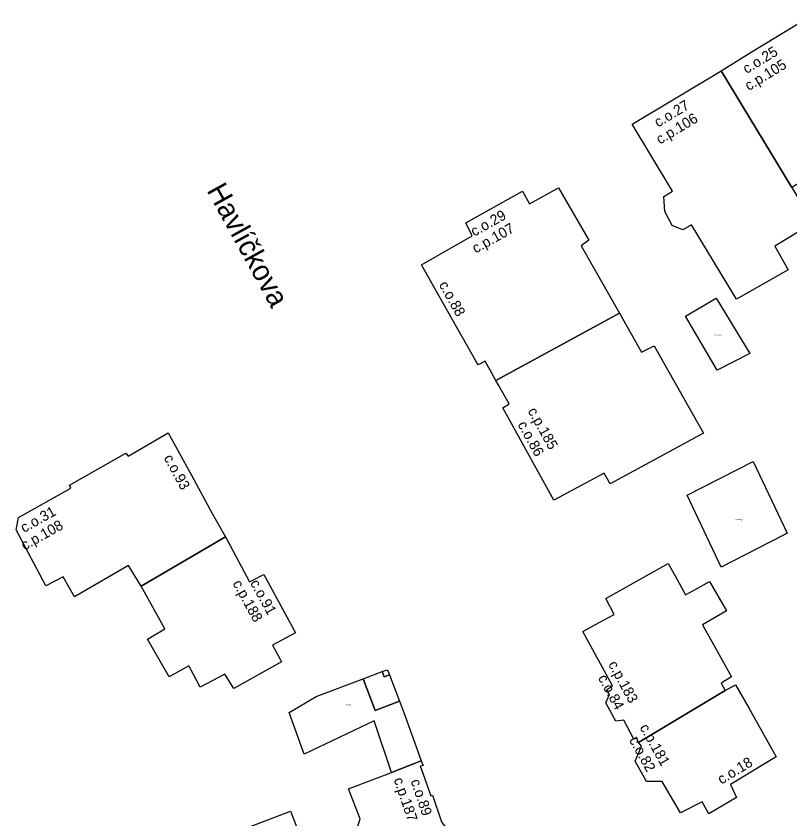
# Model space of a CAD drawing. Extents: x -600391 to -599491, y -1160176 to -1159402.
# Drawn here: x -600294.6 to -600219.9, y -1159654.1 to -1159576.6 of the extents above; entities that cross this region are included whole.
import ezdxf

# ---------------------------------------------------------------- set-up
doc = ezdxf.new("R2010")
doc.units = 0
for name, color, linetype in [('Level 10', 7, 'Continuous'), ('Level 11', 7, 'Continuous'), ('Level 12', 7, 'Continuous'), ('Level 24', 7, 'Continuous'), ('Level 25', 7, 'Continuous'), ('Level 61', 7, 'Continuous'), ('Level 62', 7, 'Continuous')]:
    doc.layers.add(name, color=color, linetype=linetype)

msp = doc.modelspace()

# ---------------------------------------------------------------- linework, layer by layer
at = {"layer": 'Level 61'}
for points in [[(-600223.41, -1159579.93), (-600217.94, -1159576.62)], [(-600226.56, -1159581.89), (-600223.41, -1159579.93)], [(-600235.15, -1159587.05), (-600226.82, -1159582.05)], [(-600226.82, -1159582.05), (-600226.56, -1159581.89)], [(-600219.75, -1159593.15), (-600226.56, -1159581.89)], [(-600226.56, -1159581.89), (-600219.75, -1159593.15)], [(-600231.24, -1159593.51), (-600235.15, -1159587.05)], [(-600251.18, -1159596.55), (-600245.74, -1159593.51)], [(-600245.74, -1159593.51), (-600245.05, -1159594.74)], [(-600245.05, -1159594.74), (-600242.26, -1159593.19)], [(-600242.26, -1159593.19), (-600239.31, -1159598.24)], [(-600232.08, -1159594.02), (-600231.24, -1159593.51)], [(-600232.01, -1159595.46), (-600232.08, -1159594.02)], [(-600231.28, -1159596.82), (-600232.01, -1159595.46)], [(-600250.59, -1159597.82), (-600251.18, -1159596.55)], [(-600229.42, -1159596.75), (-600230.25, -1159597.24)], [(-600225.09, -1159603.94), (-600229.42, -1159596.75)], [(-600217.72, -1159596.61), (-600221.38, -1159598.8)], [(-600230.25, -1159597.24), (-600231.28, -1159596.82)], [(-600255.47, -1159600.61), (-600250.59, -1159597.82)], [(-600239.31, -1159598.24), (-600240.07, -1159598.78)], [(-600240.07, -1159598.78), (-600236.37, -1159605.27)], [(-600221.38, -1159598.8), (-600220.1, -1159601.1)], [(-600255.06, -1159601.34), (-600255.47, -1159600.61)], [(-600254.31, -1159602.67), (-600255.06, -1159601.34)], [(-600220.1, -1159601.1), (-600225.09, -1159603.94)], [(-600250.16, -1159610.01), (-600254.31, -1159602.67)], [(-600229.99, -1159605.58), (-600227.04, -1159603.82)], [(-600227.04, -1159603.82), (-600223.81, -1159609.18)], [(-600248.29, -1159611.76), (-600236.37, -1159605.27)], [(-600236.37, -1159605.27), (-600248.29, -1159611.76)], [(-600236.37, -1159605.27), (-600234.94, -1159607.77)], [(-600226.93, -1159610.77), (-600229.99, -1159605.58)], [(-600234.94, -1159607.77), (-600234.25, -1159609.05)], [(-600234.25, -1159609.05), (-600233.01, -1159608.43)], [(-600233.01, -1159608.43), (-600232.11, -1159610.04)], [(-600223.81, -1159609.18), (-600226.93, -1159610.77)], [(-600249.34, -1159609.89), (-600250.01, -1159610.27)], [(-600248.29, -1159611.76), (-600249.34, -1159609.89)], [(-600250.01, -1159610.27), (-600250.16, -1159610.01)], [(-600232.11, -1159610.04), (-600228.28, -1159616.85)], [(-600248.08, -1159612.14), (-600248.29, -1159611.76)], [(-600247.02, -1159614.02), (-600248.08, -1159612.14)], [(-600247.63, -1159614.4), (-600247.02, -1159614.02)], [(-600242.69, -1159623.31), (-600247.63, -1159614.4)], [(-600283.77, -1159619.07), (-600279.92, -1159616.82)], [(-600279.92, -1159616.82), (-600278.15, -1159620.03)], [(-600228.28, -1159616.85), (-600237.27, -1159621.75)], [(-600289.41, -1159621.85), (-600283.98, -1159618.78)], [(-600283.98, -1159618.78), (-600283.77, -1159619.07)], [(-600278.15, -1159620.03), (-600277.67, -1159620.91)], [(-600229.84, -1159622.84), (-600223.48, -1159619.59)], [(-600223.48, -1159619.59), (-600220.2, -1159626.51)], [(-600237.85, -1159620.71), (-600242.69, -1159623.31)], [(-600237.27, -1159621.75), (-600237.85, -1159620.71)], [(-600277.67, -1159620.91), (-600275.66, -1159624.6)], [(-600294.33, -1159624.97), (-600289.29, -1159622.14)], [(-600289.29, -1159622.14), (-600289.41, -1159621.85)], [(-600226.57, -1159629.76), (-600229.84, -1159622.84)], [(-600275.66, -1159624.6), (-600274.39, -1159626.85)], [(-600294.58, -1159626.18), (-600294.33, -1159624.97)], [(-600291.7, -1159631.56), (-600294.58, -1159626.18)], [(-600282.5, -1159631.62), (-600274.39, -1159626.85)], [(-600274.39, -1159626.85), (-600282.5, -1159631.62)], [(-600274.39, -1159626.85), (-600274.16, -1159627.27)], [(-600220.6, -1159626.71), (-600226.57, -1159629.76)], [(-600220.2, -1159626.51), (-600220.6, -1159626.71)], [(-600274.16, -1159627.27), (-600272.05, -1159631.18)], [(-600283.72, -1159629.61), (-600288.93, -1159632.63)], [(-600282.5, -1159631.62), (-600283.72, -1159629.61)], [(-600237.68, -1159632.8), (-600231.67, -1159629.41)], [(-600231.67, -1159629.41), (-600231, -1159630.62)], [(-600290.03, -1159630.71), (-600291.7, -1159631.56)], [(-600288.93, -1159632.63), (-600290.03, -1159630.71)], [(-600272.05, -1159631.18), (-600270.69, -1159630.49)], [(-600270.69, -1159630.49), (-600267.61, -1159636.1)], [(-600231, -1159630.62), (-600229.99, -1159632.43)], [(-600280.22, -1159635.71), (-600282.5, -1159631.62)], [(-600228.94, -1159631.85), (-600227.68, -1159631.16)], [(-600227.68, -1159631.16), (-600226.04, -1159633.98)], [(-600229.99, -1159632.43), (-600228.94, -1159631.85)], [(-600236.87, -1159634.33), (-600237.68, -1159632.8)], [(-600238.32, -1159635.1), (-600236.87, -1159634.33)], [(-600226.04, -1159633.98), (-600228.37, -1159635.33)], [(-600239.92, -1159635.98), (-600238.32, -1159635.1)], [(-600228.37, -1159635.33), (-600225.56, -1159640.36)], [(-600281.91, -1159636.71), (-600280.22, -1159635.71)], [(-600267.61, -1159636.1), (-600269.84, -1159637.3)], [(-600237.04, -1159641.22), (-600239.92, -1159635.98)], [(-600279.82, -1159640.36), (-600281.91, -1159636.71)], [(-600269.84, -1159637.3), (-600269.1, -1159638.65)], [(-600277.91, -1159639.28), (-600278.65, -1159639.72)], [(-600277.46, -1159640.14), (-600277.91, -1159639.28)], [(-600268.97, -1159638.89), (-600273.58, -1159641.47)], [(-600269.1, -1159638.65), (-600268.97, -1159638.89)], [(-600278.65, -1159639.72), (-600279.82, -1159640.36)], [(-600276.81, -1159641.34), (-600277.46, -1159640.14)], [(-600274.43, -1159640.09), (-600276.81, -1159641.34)], [(-600273.58, -1159641.47), (-600274.43, -1159640.09)], [(-600261.1, -1159640.54), (-600259.26, -1159639.85)], [(-600259.26, -1159639.85), (-600258.75, -1159639.66)], [(-600259.06, -1159640.34), (-600259.26, -1159639.85)], [(-600259.26, -1159639.85), (-600259.06, -1159640.34)], [(-600258.56, -1159640.15), (-600259.06, -1159640.34)], [(-600259.06, -1159640.34), (-600258.56, -1159640.15)], [(-600258.75, -1159639.66), (-600258.56, -1159640.15)], [(-600258.56, -1159640.15), (-600257.59, -1159642.7)], [(-600265.63, -1159642.24), (-600261.1, -1159640.54)], [(-600261.1, -1159640.54), (-600259.95, -1159643.59)], [(-600259.95, -1159643.59), (-600261.1, -1159640.54)], [(-600225.56, -1159640.36), (-600226.56, -1159640.95)], [(-600237.61, -1159641.61), (-600237.04, -1159641.22)], [(-600237.33, -1159642.07), (-600237.61, -1159641.61)], [(-600234.53, -1159646.7), (-600226.16, -1159641.67)], [(-600226.16, -1159641.67), (-600234.53, -1159646.7)], [(-600226.56, -1159640.95), (-600226.16, -1159641.67)], [(-600226.16, -1159641.67), (-600225.17, -1159641.11)], [(-600225.17, -1159641.11), (-600223.86, -1159643.39)], [(-600268.23, -1159643.8), (-600265.63, -1159642.24)], [(-600237.67, -1159642.86), (-600237.33, -1159642.07)], [(-600259.95, -1159643.59), (-600257.59, -1159642.7)], [(-600257.59, -1159642.7), (-600259.95, -1159643.59)], [(-600257.59, -1159642.7), (-600257.18, -1159643.79)], [(-600236.71, -1159644.63), (-600237.67, -1159642.86)], [(-600266.79, -1159647.81), (-600268.23, -1159643.8)], [(-600257.18, -1159643.79), (-600255.69, -1159647.89)], [(-600223.86, -1159643.39), (-600221.27, -1159648.07)], [(-600260.04, -1159644.61), (-600266.79, -1159647.81)], [(-600258.35, -1159649.57), (-600260.04, -1159644.61)], [(-600235.95, -1159644.53), (-600236.71, -1159644.63)], [(-600234.97, -1159646.35), (-600235.95, -1159644.53)], [(-600234.73, -1159646.2), (-600234.97, -1159646.35)], [(-600234.53, -1159646.7), (-600234.73, -1159646.2)], [(-600234.85, -1159648.48), (-600234.24, -1159647.04)], [(-600234.24, -1159647.04), (-600234.53, -1159646.7)], [(-600255.69, -1159647.89), (-600255.49, -1159648.45)], [(-600258.35, -1159649.57), (-600255.49, -1159648.45)], [(-600255.49, -1159648.45), (-600258.35, -1159649.57)], [(-600255.49, -1159648.45), (-600255.32, -1159648.91)], [(-600233.76, -1159650.43), (-600234.85, -1159648.48)], [(-600221.27, -1159648.07), (-600225.65, -1159650.73)], [(-600255.32, -1159648.91), (-600255.59, -1159648.97)], [(-600255.59, -1159648.97), (-600255.48, -1159649.3)], [(-600255.48, -1159649.3), (-600254.57, -1159651.84)], [(-600262.51, -1159651.15), (-600258.35, -1159649.57)], [(-600232.26, -1159650.45), (-600233.76, -1159650.43)], [(-600230.47, -1159653.48), (-600232.26, -1159650.45)], [(-600225.65, -1159650.73), (-600225.07, -1159652)], [(-600261.4, -1159654.06), (-600262.51, -1159651.15)], [(-600254.57, -1159651.84), (-600254.41, -1159651.78)], [(-600254.41, -1159651.78), (-600253.55, -1159654.34)], [(-600228.4, -1159652.41), (-600230.47, -1159653.48)], [(-600227.76, -1159653.58), (-600228.4, -1159652.41)], [(-600225.07, -1159652), (-600227.76, -1159653.58)], [(-600274.92, -1159655.92), (-600268.09, -1159653.3)], [(-600268.09, -1159653.3), (-600266.93, -1159656.35)]]:
    msp.add_lwpolyline(points, dxfattribs=at)
at = {"layer": 'Level 62'}
for points in [[(-600217.94, -1159576.62), (-600214.92, -1159581.75), (-600213.47, -1159580.87), (-600211.53, -1159584.06), (-600212.68, -1159584.71), (-600211.34, -1159586.87), (-600211.09, -1159587.49), (-600211.09, -1159588.31), (-600211.26, -1159588.86), (-600211.32, -1159588.99), (-600211.62, -1159589.45), (-600211.99, -1159589.82), (-600212.41, -1159590.07), (-600213, -1159590.28), (-600213.53, -1159589.42), (-600219.75, -1159593.15), (-600226.56, -1159581.89), (-600223.41, -1159579.93), (-600217.94, -1159576.62)], [(-600218.37, -1159595.46), (-600217.72, -1159596.61), (-600221.38, -1159598.8), (-600220.1, -1159601.1), (-600225.09, -1159603.94), (-600229.42, -1159596.75), (-600230.25, -1159597.24), (-600231.28, -1159596.82), (-600232.01, -1159595.46), (-600232.08, -1159594.02), (-600231.24, -1159593.51), (-600235.15, -1159587.05), (-600226.82, -1159582.05), (-600226.56, -1159581.89), (-600219.75, -1159593.15), (-600218.37, -1159595.46)], [(-600239.31, -1159598.24), (-600240.07, -1159598.78), (-600236.37, -1159605.27), (-600248.29, -1159611.76), (-600249.34, -1159609.89), (-600250.01, -1159610.27), (-600250.16, -1159610.01), (-600254.31, -1159602.67), (-600255.06, -1159601.34), (-600255.47, -1159600.61), (-600250.59, -1159597.82), (-600251.18, -1159596.55), (-600245.74, -1159593.51), (-600245.05, -1159594.74), (-600242.26, -1159593.19), (-600239.31, -1159598.24)], [(-600223.81, -1159609.18), (-600226.93, -1159610.77), (-600229.99, -1159605.58), (-600227.04, -1159603.82), (-600223.81, -1159609.18)], [(-600236.37, -1159605.27), (-600234.94, -1159607.77), (-600234.25, -1159609.05), (-600233.01, -1159608.43), (-600232.11, -1159610.04), (-600228.28, -1159616.85), (-600237.27, -1159621.75), (-600237.85, -1159620.71), (-600242.69, -1159623.31), (-600247.63, -1159614.4), (-600247.02, -1159614.02), (-600248.08, -1159612.14), (-600248.29, -1159611.76), (-600236.37, -1159605.27)], [(-600274.39, -1159626.85), (-600282.5, -1159631.62), (-600283.72, -1159629.61), (-600288.93, -1159632.63), (-600290.03, -1159630.71), (-600291.7, -1159631.56), (-600294.58, -1159626.18), (-600294.33, -1159624.97), (-600289.29, -1159622.14), (-600289.41, -1159621.85), (-600283.98, -1159618.78), (-600283.77, -1159619.07), (-600279.92, -1159616.82), (-600278.15, -1159620.03), (-600277.67, -1159620.91), (-600275.66, -1159624.6), (-600274.39, -1159626.85)], [(-600229.84, -1159622.84), (-600223.48, -1159619.59), (-600220.2, -1159626.51), (-600220.6, -1159626.71), (-600226.57, -1159629.76), (-600229.84, -1159622.84)], [(-600278.65, -1159639.72), (-600279.82, -1159640.36), (-600281.91, -1159636.71), (-600280.22, -1159635.71), (-600282.5, -1159631.62), (-600274.39, -1159626.85), (-600274.16, -1159627.27), (-600272.05, -1159631.18), (-600270.69, -1159630.49), (-600267.61, -1159636.1), (-600269.84, -1159637.3), (-600269.1, -1159638.65), (-600268.97, -1159638.89), (-600273.58, -1159641.47), (-600274.43, -1159640.09), (-600276.81, -1159641.34), (-600277.46, -1159640.14), (-600277.91, -1159639.28), (-600278.65, -1159639.72)], [(-600228.94, -1159631.85), (-600227.68, -1159631.16), (-600226.04, -1159633.98), (-600228.37, -1159635.33), (-600225.56, -1159640.36), (-600226.56, -1159640.95), (-600226.16, -1159641.67), (-600234.53, -1159646.7), (-600234.73, -1159646.2), (-600234.97, -1159646.35), (-600235.95, -1159644.53), (-600236.71, -1159644.63), (-600237.67, -1159642.86), (-600237.33, -1159642.07), (-600237.61, -1159641.61), (-600237.04, -1159641.22), (-600239.92, -1159635.98), (-600238.32, -1159635.1), (-600236.87, -1159634.33), (-600237.68, -1159632.8), (-600231.67, -1159629.41), (-600231, -1159630.62), (-600229.99, -1159632.43), (-600228.94, -1159631.85)], [(-600258.56, -1159640.15), (-600257.59, -1159642.7), (-600259.95, -1159643.59), (-600261.1, -1159640.54), (-600259.26, -1159639.85), (-600259.06, -1159640.34), (-600258.56, -1159640.15)], [(-600258.56, -1159640.15), (-600259.06, -1159640.34), (-600259.26, -1159639.85), (-600258.75, -1159639.66), (-600258.56, -1159640.15)], [(-600258.35, -1159649.57), (-600260.04, -1159644.61), (-600266.79, -1159647.81), (-600268.23, -1159643.8), (-600265.63, -1159642.24), (-600261.1, -1159640.54), (-600259.95, -1159643.59), (-600257.59, -1159642.7), (-600257.18, -1159643.79), (-600255.69, -1159647.89), (-600255.49, -1159648.45), (-600258.35, -1159649.57)], [(-600226.16, -1159641.67), (-600225.17, -1159641.11), (-600223.86, -1159643.39), (-600221.27, -1159648.07), (-600225.65, -1159650.73), (-600225.07, -1159652), (-600227.76, -1159653.58), (-600228.4, -1159652.41), (-600230.47, -1159653.48), (-600232.26, -1159650.45), (-600233.76, -1159650.43), (-600234.85, -1159648.48), (-600234.24, -1159647.04), (-600234.53, -1159646.7), (-600226.16, -1159641.67)], [(-600263.57, -1159655.8), (-600261.71, -1159655.09), (-600261.4, -1159654.06), (-600262.51, -1159651.15), (-600258.35, -1159649.57), (-600255.49, -1159648.45), (-600255.32, -1159648.91), (-600255.59, -1159648.97), (-600255.48, -1159649.3), (-600254.57, -1159651.84), (-600254.41, -1159651.78), (-600253.55, -1159654.34), (-600252.98, -1159655.06), (-600252.44, -1159655.89), (-600252.06, -1159657.09), (-600251.78, -1159658), (-600251.89, -1159659.27), (-600249.71, -1159664.91), (-600257.5, -1159667.81), (-600259.33, -1159668.5), (-600263.9, -1159655.92), (-600263.57, -1159655.8)], [(-600268.09, -1159653.3), (-600266.93, -1159656.35), (-600266.16, -1159656.79), (-600264.26, -1159656.06), (-600263.9, -1159655.92), (-600259.33, -1159668.5), (-600261.39, -1159669.26), (-600269.13, -1159672.15), (-600271.23, -1159666.16), (-600271.98, -1159665.45), (-600272.49, -1159664.66), (-600272.91, -1159663.6), (-600273.06, -1159662.75), (-600273.02, -1159661.88), (-600274.19, -1159658.74), (-600273.93, -1159658.6), (-600274.92, -1159655.92), (-600268.09, -1159653.3)]]:
    msp.add_lwpolyline(points, dxfattribs=at)

# ---------------------------------------------------------------- texts
at = {"layer": 'Level 10'}
for s, rotation, p in [('c.o.25', 31.43934, (-600224.101, -1159582.22)), ('c.o.27', 30.99225, (-600232.647, -1159587.382)), ('c.o.29', 29.19763, (-600250.383, -1159597.908)), ('c.o.88', 299.10246, (-600253.819, -1159602.523)), ('c.o.86', 299.00508, (-600246.225, -1159616.017)), ('c.o.93', 298.56656, (-600280.363, -1159619.224)), ('c.o.31', 29.31562, (-600293.807, -1159626.483)), ('c.o.91', 298.76913, (-600272.027, -1159631.294)), ('c.o.84', 298.47694, (-600238.473, -1159640.448)), ('c.o.82', 299.20263, (-600235.476, -1159646.452)), ('c.o.18', 31.2723, (-600226.535, -1159650.757)), ('c.o.89', 288.6397, (-600256.527, -1159650.399))]:
    msp.add_text(s, height=1, rotation=rotation, dxfattribs=at).set_placement(p)
at = {"layer": 'Level 11'}
msp.add_text('Havlíčkova', height=2, rotation=298.81899, dxfattribs=at).set_placement((-600276.227, -1159593.425))
at = {"layer": 'Level 12'}
for s, rotation, p in [('c.p.105', 31.43934, (-600223.897, -1159583.855)), ('c.p.106', 30.99225, (-600232.467, -1159589.025)), ('c.p.107', 29.19763, (-600250.238, -1159599.538)), ('c.p.185', 299.00508, (-600245.251, -1159614.704)), ('c.p.108', 29.31562, (-600293.756, -1159628.175)), ('c.p.188', 298.76913, (-600273.718, -1159631.331)), ('c.p.183', 298.47694, (-600237.484, -1159639.138)), ('c.p.181', 299.20263, (-600234.456, -1159645.224)), ('c.p.187', 288.6397, (-600258.165, -1159650.248))]:
    msp.add_text(s, height=1, rotation=rotation, dxfattribs=at).set_placement(p)
at = {"layer": 'Level 24'}
msp.add_text('c.z.212', height=0.1, dxfattribs=at).set_placement((-600262.749, -1159643.087))
at = {"layer": 'Level 25'}
for s, p in [('c.pp.106_A', (-600227.203, -1159607.407)), ('c.pp.183_A', (-600225.163, -1159625.217))]:
    msp.add_text(s, height=0.1, dxfattribs=at).set_placement(p)

doc.saveas('drawing.dxf')
